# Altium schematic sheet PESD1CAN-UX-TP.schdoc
size 127 x 101 mm
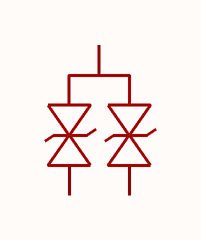
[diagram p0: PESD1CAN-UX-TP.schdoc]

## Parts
D?  pesd1can-ux  [SOT-323-3_L2.0-W1.3-P1.30-LS2.1-BR]  (value not drawn)

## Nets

Not connected (* = marked no-connect by the designer): D? 1 2 3

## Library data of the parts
D? = pesd1can-ux: 反向截止电压(Vrwm):24V;钳位电压:50V;峰值脉冲电流(Ipp):3A@8/20us;峰值脉冲功率(Ppp):150W@8/20us;击穿电压:25V;; Manufacturer: TECH PUBLIC(台舟); Symbol: PESD1CAN-UX-TP; AddInBom: yes; ModelId: 59529c0d6fc749f28f2d0659e12986b4; ModelName: SOT-323-3_L2.0-W1.3-H1.0-LS2.1-P1.30; ModelTransform: 78.74,82.677,0,90,0,0,0.0005,0,0; Reverse Stand-Off Voltage (Vrwm): 24V; Clamping Voltage: 50V; Voltage - Breakdown: 25V; Reverse Leakage Current (Ir): 80nA; level of protection: IEC 61000-4-4；IEC 61000-4-5；IEC 61000-4-2; Type: ESD; Junction Capacitance: 10pF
